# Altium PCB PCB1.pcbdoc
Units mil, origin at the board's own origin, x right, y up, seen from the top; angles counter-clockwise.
Board outline 3149.61 x 1574.8 mil, 2 copper layers (Top Layer, Bottom Layer); 16 components, 32 nets, 99 pads, 36 vias.
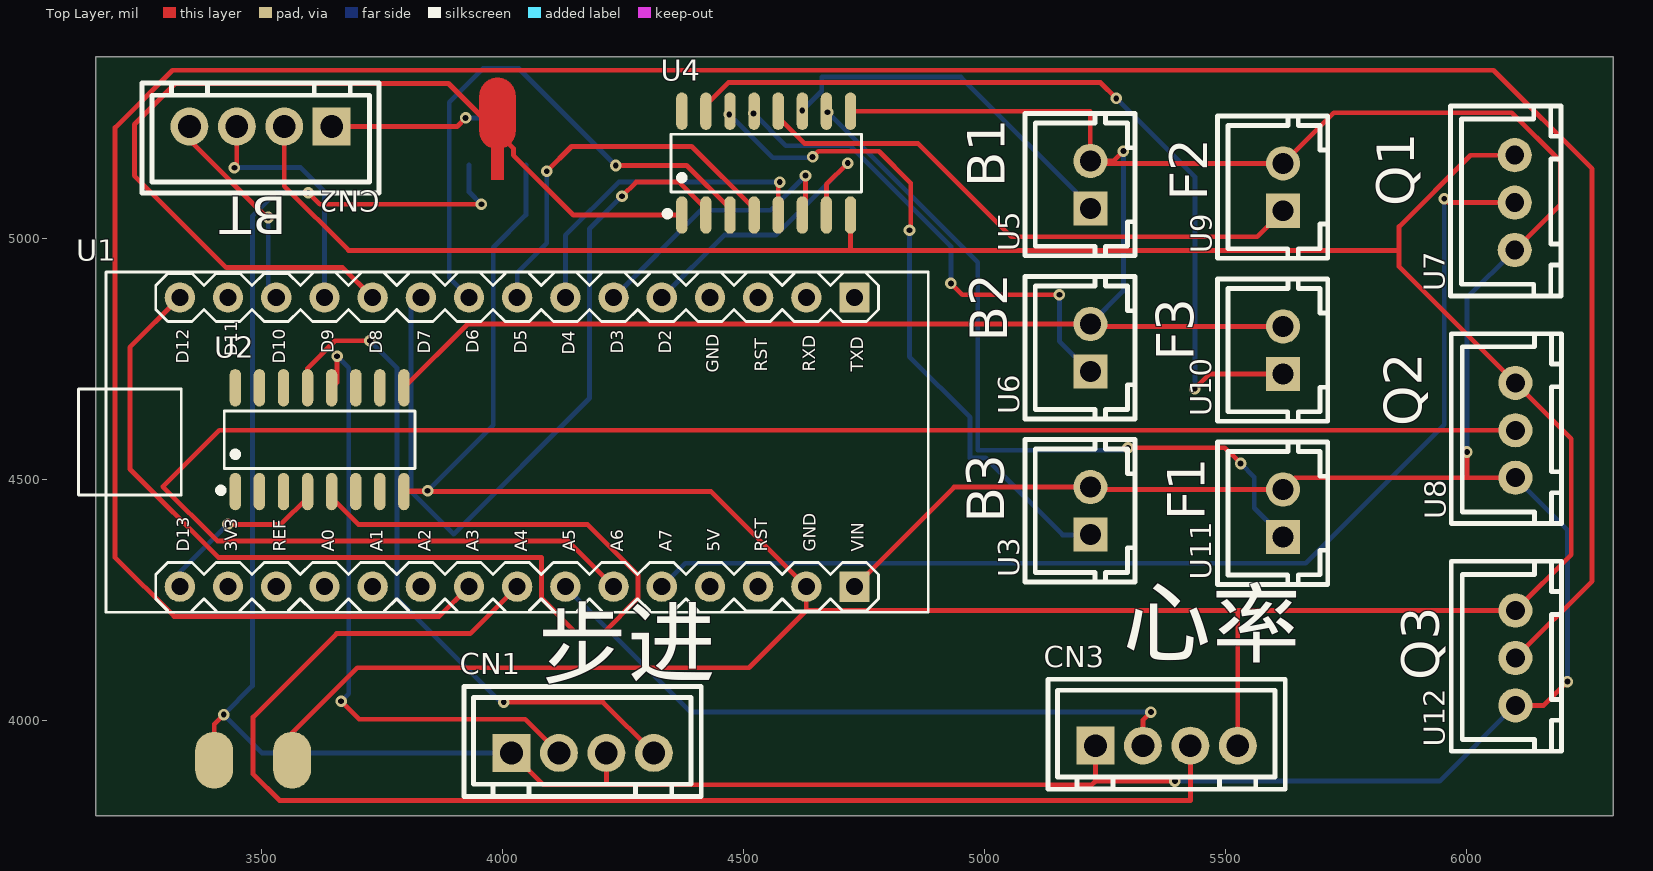
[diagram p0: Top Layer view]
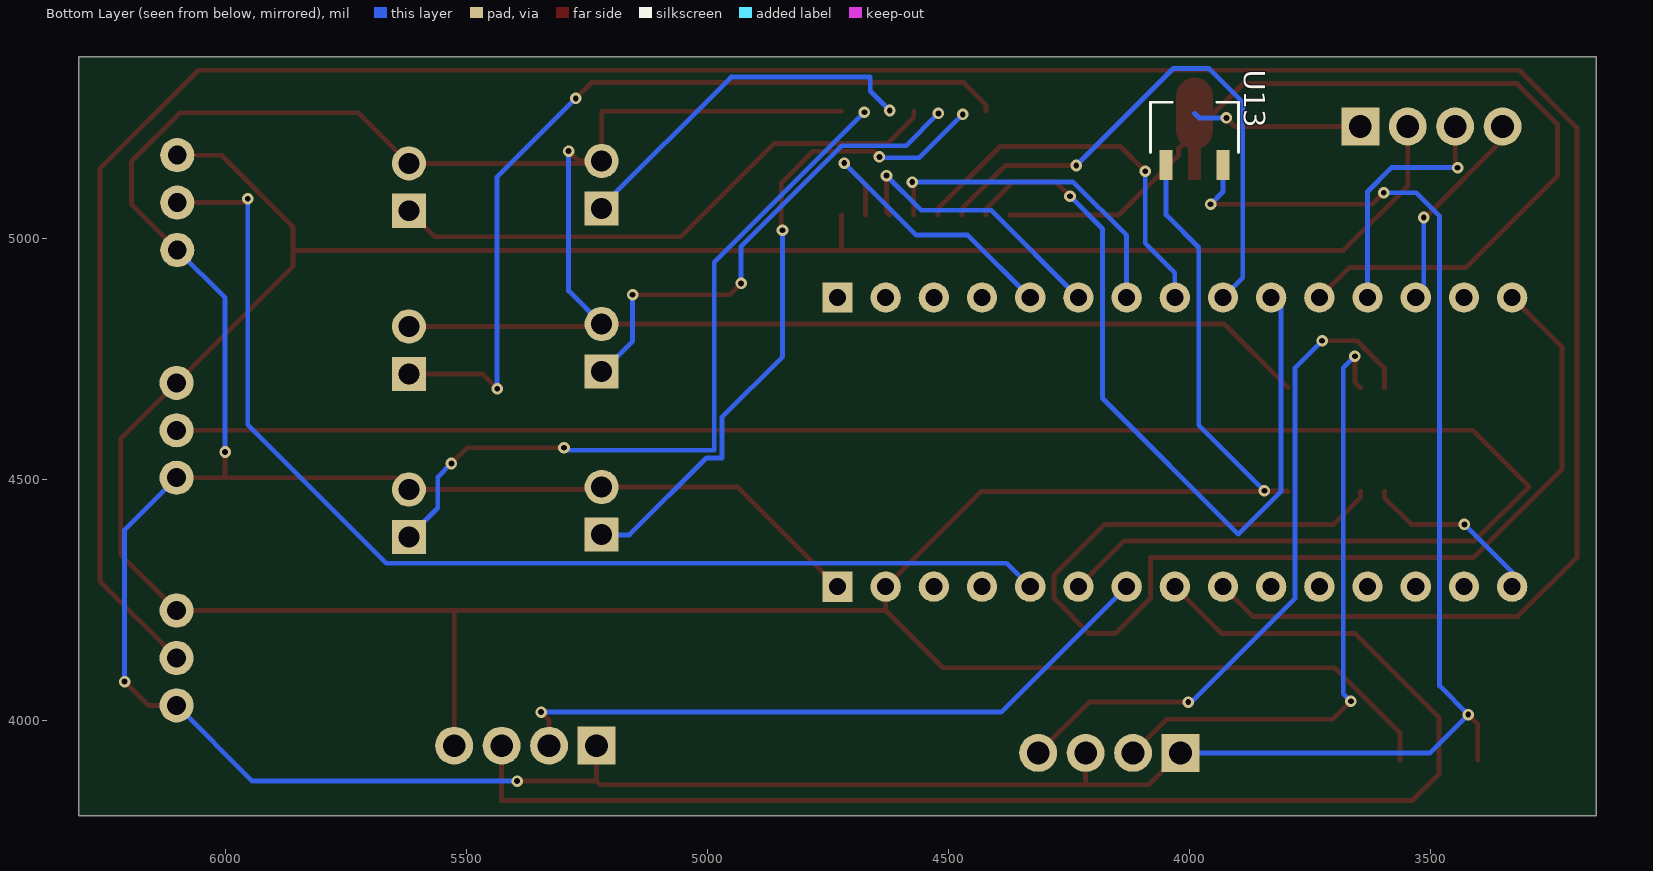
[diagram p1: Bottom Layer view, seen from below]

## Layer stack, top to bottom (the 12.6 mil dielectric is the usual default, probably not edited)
Top Solder: solder mask 0.4, Solder Resist, Dk 3.5
Top Layer: signal copper 1.4
Dielectric 1: dielectric 12.6, FR-4, Dk 4.8
Bottom Layer: signal copper 1.4
Bottom Solder: solder mask 0.4, Solder Resist, Dk 3.5

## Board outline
3154.76,3802.62 6304.37,3802.62 6304.37,5377.42 3154.76,5377.42

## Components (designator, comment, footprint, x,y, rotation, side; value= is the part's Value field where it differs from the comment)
CN1 "" CONN-TH_XH-4A 4165.55,3932.62 r0 top
CN2 "" CONN-TH_XH-4A 3497.17,5232.43 r180 top
CN3 "" CONN-TH_XH-4A 5377.4,3947.62 r0 top
U1 "" COMM-TH_ARDUINO_NANO 4029.76,4577.62 r0 top
U2 "" SOIC-16_L9.9-W3.9-P1.27-LS6.0-BL 3619.76,4582.62 r0 top
U3 "" CONN-TH_2P-P2.50_XH-2A_3045048 5219.09,4435.1 r90 top
U4 "" SOIC-16_L9.9-W3.9-P1.27-LS6.0-BL 4546.43,5156.5 r0 top
U5 "" CONN-TH_2P-P2.50_XH-2A_3045048 5219.09,5111.79 r90 top
U6 "" CONN-TH_2P-P2.50_XH-2A_3045048 5219.09,4773.44 r90 top
U7 "" CONN-TH_XH-3A 6099.76,5074.56 r90 top
U8 "" CONN-TH_XH-3A 6101.09,4602.12 r90 top
U9 "" CONN-TH_2P-P2.50_XH-2A_3045048 5619.09,5106.75 r90 top
U10 "" CONN-TH_2P-P2.50_XH-2A_3045048 5619.09,4768.41 r90 top
U11 "" CONN-TH_2P-P2.50_XH-2A_3045048 5619.09,4430.06 r90 top
U12 "" CONN-TH_XH-3A 6101.09,4129.67 r90 top
U13 "" SOT-89-3_L4.5-W2.5-P1.50-LS4.2-BR 3988.88,5206.15 r270 bottom

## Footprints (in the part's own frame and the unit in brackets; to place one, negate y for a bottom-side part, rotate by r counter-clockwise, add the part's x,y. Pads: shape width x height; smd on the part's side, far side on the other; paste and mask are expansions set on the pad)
COMM-TH_ARDUINO_NANO [mm]
  rect 1.6x1.6 hole 0.9: 1(17.78,7.62) 30(17.78,-7.62)
  round 1.6 hole 0.9: 2(15.24,7.62) 4(10.16,7.62) 6(5.08,7.62) 8(0,7.62) 10(-5.08,7.62) 12(-10.16,7.62) 14(-15.24,7.62) 15(-17.78,7.62) 16(-17.78,-7.62) 18(-12.7,-7.62) 20(-7.62,-7.62) 22(-2.54,-7.62) 24(2.54,-7.62) 26(7.62,-7.62) 28(12.7,-7.62) 29(15.24,-7.62)
  round 1.6 hole 0.9 copper offset 0,0: 3(12.7,7.62)
  round 1.6 hole 0.9 copper offset 0.001,0: 5(7.619,7.62) 7(2.539,7.62) 9(-2.541,7.62) 11(-7.621,7.62) 13(-12.701,7.62)
  round 1.6 hole 0.9 copper offset -0.001,0: 17(-15.239,-7.62) 19(-10.159,-7.62) 21(-5.079,-7.62) 23(0.001,-7.62) 25(5.081,-7.62) 27(10.161,-7.62)
  silkscreen extent -23.11,-8.97 21.67,8.97
CONN-TH_2P-P2.50_XH-2A_3045048 [mm]
  rect 1.8x1.8 hole 1.1: 1(-1.25,0)
  round 1.8 hole 1.1: 2(1.25,0)
  silkscreen extent -3.75,-2.35 3.75,3.45
CONN-TH_XH-3A [mm]
  round 1.8 hole 1: 1(-2.5,0) 2(0,0) 3(2.5,0)
  silkscreen extent -4.92,-2.44 5.09,3.38
CONN-TH_XH-4A [mm]
  rect 2x2 hole 1.2: 1(-3.75,0)
  round 2 hole 1.2: 2(-1.25,0) 3(1.25,0) 4(3.75,0)
  silkscreen extent -6.25,-2.3 6.25,3.5
SOIC-16_L9.9-W3.9-P1.27-LS6.0-BL [mil]
  oval 23.7x77.6 smd: 1(-175,-107.7) 2(-125,-107.7) 3(-75,-107.7) 4(-25,-107.7) 5(25,-107.7) 6(75,-107.7) 7(125,-107.7) 8(175,-107.7) 9(175,107.7) 10(125,107.7) 11(75,107.7) 12(25,107.7) 13(-25,107.7) 14(-75,107.7) 15(-125,107.7) 16(-175,107.7)
  silkscreen extent -211,-111 198,60
SOT-89-3_L4.5-W2.5-P1.50-LS4.2-BR [mm]
  rect 1.575x0.672 smd: 1(1.356,-1.5) 3(1.356,1.5)
  Bottom Layer region: -2.283,0.95 -0.429,0.95 -0.384,0.949 -0.34,0.946 -0.296,0.94 -0.252,0.933 -0.208,0.924 -0.165,0.912 -0.123,0.899 -0.081,0.884 -0.04,0.866 0,0.847 0.04,0.826 0.078,0.803 0.115,0.779 0.151,0.752 0.185,0.724 0.219,0.695 0.251,0.664 0.281,0.631 0.31,0.597 0.337,0.562 0.362,0.525 0.386,0.488 0.408,0.449 0.428,0.409 0.447,0.33 2.144,0.33 2.144,-0.33 0.447,-0.33 0.428,-0.409 0.408,-0.449 0.386,-0.488 0.362,-0.526 0.337,-0.562 0.31,-0.597 0.281,-0.631 0.251,-0.664 0.219,-0.695 0.185,-0.725 0.151,-0.753 0.115,-0.779 0.078,-0.804 0.04,-0.827 0,-0.848 -0.04,-0.867 -0.081,-0.884 -0.123,-0.899 -0.165,-0.913 -0.208,-0.924 -0.252,-0.934 -0.296,-0.941 -0.34,-0.946 -0.384,-0.949 -0.429,-0.95 -2.283,-0.95 -2.328,-0.949 -2.372,-0.946 -2.416,-0.941 -2.46,-0.934 -2.504,-0.924 -2.547,-0.913 -2.589,-0.899 -2.631,-0.884 -2.672,-0.867 -2.713,-0.848 -2.752,-0.827 -2.79,-0.804 -2.827,-0.779 -2.863,-0.753 -2.898,-0.725 -2.931,-0.695 -2.963,-0.664 -2.993,-0.631 -3.022,-0.597 -3.049,-0.562 -3.075,-0.526 -3.098,-0.488 -3.12,-0.449 -3.141,-0.409 -3.159,-0.369 -3.175,-0.327 -3.189,-0.285 -3.202,-0.242 -3.212,-0.199 -3.22,-0.155 -3.227,-0.111 -3.231,-0.067 -3.233,-0.022 -3.233,0.022 -3.231,0.067 -3.227,0.111 -3.22,0.155 -3.212,0.199 -3.202,0.242 -3.189,0.285 -3.175,0.327 -3.159,0.369 -3.141,0.409 -3.12,0.449 -3.098,0.488 -3.075,0.525 -3.049,0.562 -3.022,0.597 -2.993,0.631 -2.963,0.664 -2.931,0.695 -2.898,0.724 -2.863,0.752 -2.827,0.779 -2.79,0.803 -2.752,0.826 -2.713,0.847 -2.672,0.866 -2.631,0.884 -2.589,0.899 -2.547,0.912 -2.504,0.924 -2.46,0.933 -2.416,0.94 -2.372,0.946 -2.328,0.949
  silkscreen extent -1.95,-2.33 0.7,2.33

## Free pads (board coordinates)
  oval 78.74x118.11 smd: ""(3401.05,3917.38) ""(3562.69,3917.38)

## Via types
v1: diameter 24.02, hole 12.01, Top Layer to Bottom Layer, 36 vias

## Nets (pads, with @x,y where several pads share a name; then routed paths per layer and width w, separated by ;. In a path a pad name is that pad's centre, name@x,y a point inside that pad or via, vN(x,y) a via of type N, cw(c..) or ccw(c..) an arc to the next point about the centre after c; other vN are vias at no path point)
$1N1078: U1.5 U2.7 U4.7 | length 627.3
  Top Layer w10: U4.7 4671.43,5112.35 v1(4715.59,5156.5)
  Bottom Layer w10: U1.5@4329.76,4877.62 4459.25,5007.1 4566.18,5007.1 v1(4715.59,5156.5)
$1N1083: U1.6 U2.6 U4.6 | length 587.4
  Top Layer w10: U4.6 4627.98,5055.35 v1(4627.98,5130.55)
  Bottom Layer w10: U1.6 4410.74,5058.59 4556.02,5058.59 v1(4627.98,5130.55)
$1N1088: U1.7 U4.5 | length 689
  Top Layer w10: U4.5 4571.43,5113.98 v1(4574.55,5117.1)
  Bottom Layer w10: U1.7@4129.76,4877.62 4129.76,5006.45 4240.41,5117.1 v1(4574.55,5117.1)
$1N1093: U1.8 U4.4 | length 805.3
  Top Layer w10: v1(4091.22,5139.75) 4142.47,5191 4391.89,5191 4521.43,5061.45 U4.4
  Bottom Layer w10: U1.8 4029.76,4928.87 4091.22,4990.32 v1(4091.22,5139.75)
$1N1098: U1.9 U2.3 U4.3 | length 1166.7
  Top Layer w10: v1(4234.42,5151.59) 4381.3,5151.59 4471.43,5061.45 U4.3
  Bottom Layer w10: U1.9@3929.76,4877.62 3888.93,4918.45 3888.93,5282.87 3958.58,5352.52 4033.49,5352.52 v1(4234.42,5151.59)
$1N1103: U1.10 U2.2 U4.2 | length 1603.8
  Top Layer w10: v1(4247.17,5087.85) 4276.42,5117.1 4365.79,5117.1 4421.43,5061.45 U4.2
  Bottom Layer w10: U1.10 3809.53,4857.38 3809.53,4474.89 3897.7,4386.71 4179.76,4668.77 4179.76,5020.44 v1(4247.17,5087.85)
$1N1108: U1.11 U2.1 U4.1 | length 1997.7
  Top Layer w10: U1.11@3729.76,4877.62 3667.74,4939.64 3426.4,4939.64 3235.36,5130.68 3235.36,5236.61 3320.46,5321.71 3887.25,5321.71 4021.88,5187.08 4021.88,5173.07 4146.15,5048.8 U4.1
$1N1790: U1.15 U2.5 | length 2437.4
  Top Layer w10: U1.15 3226.15,4774 3226.15,4521.73 3409.69,4338.19 4080.22,4338.19 4080.22,4253.31 4153.27,4180.26 4207.17,4180.26 4280.22,4253.31 4280.22,4301.92 4175.33,4406.81 3700.22,4406.81 3644.76,4462.27 U2.5
$1N1795: U1.16 U2.4 | length 371.8
  Top Layer w10: v1(3428.75,4406.81) 3539.31,4406.81 3594.76,4462.27 U2.4
  Bottom Layer w10: U1.16 3329.76,4307.82 v1(3428.75,4406.81)
$1N2846: CN1.4 U2.13 | length 1416.9
  Top Layer w10: U2.13 3594.76,4730.76 3651.74,4787.73 v1(3724.13,4787.73) ; v1(4002.02,4038.08) 4207.73,4038.08 CN1.4
  Bottom Layer w10: v1(3724.13,4787.73) 3780.22,4731.64 3780.22,4253.31 3995.46,4038.08 v1(4002.02,4038.08)
$1N4027: U1.26 U7.2 | length 2381.4
  Top Layer w10: v1(5953.58,5082.61) 5961.64,5074.55 U7.2
  Bottom Layer w10: U1.26 4378.36,4326.22 5665.93,4326.22 5953.58,4613.86 v1(5953.58,5082.61)
$1N4520: CN3.2 U1.24 | length 1399.4
  Top Layer w10: CN3.2 5328.19,4000.83 v1(5344.73,4017.37)
  Bottom Layer w10: U1.24 4390.01,4017.37 v1(5344.73,4017.37)
$1N4548: CN3.3 U1.23 | length 2859.5
  Top Layer w10: U1.23 3932.41,4180.26 3655.07,4180.26 3481.87,4007.06 3481.87,3888.76 3536.77,3833.86 5426.61,3833.86 CN3.3
$1N4816: CN2.1 | length 355.3
  Top Layer w10: CN2.1 3904.91,5232.43 v1(3922.71,5250.23)
  Bottom Layer w10: v1(3922.71,5250.23) 3979.58,5250.23 3988.89,5259.54
$1N4934: CN2.4 U1.13 | length 431.1
  Top Layer w10: CN2.4 3349.53,5204.61 3510.45,5043.7 v1(3513.3,5043.7)
  Bottom Layer w10: v1(3513.3,5043.7) 3513.3,4894.08 U1.13@3529.76,4877.62
$1N4935: CN2.3 U1.12 | length 514.6
  Top Layer w10: v1(3443.06,5147.1) 3447.96,5152 CN2.3
  Bottom Layer w10: v1(3443.06,5147.1) 3580.27,5147.1 3629.76,5097.6 U1.12
+5V: CN1.1 CN1.3 CN3.1 pad.@3401.05,3917.38 U1.30 U2.9 U3.2 U4.9 U5.2 U6.2 U7.1 U8.1 U9.2 U10.2 U11.2 U12.1 U13.3 | length 11520
  Top Layer w10: pad.@3401.05,3917.38 3401.05,3992.49 v1(3420.65,4012.09) ; v1(3596.2,5095.15) 3620.32,5071.03 v1(3955.41,5071.03) ; U2.9 3927.1,4822.65 U6.2 5224.13,4817.62 U10.2 ; CN1.1 4083.98,3866.55 4214.76,3866.55 ; CN1.3 4214.76,3866.55 ; U4.9 5219.09,5264.2 U5.2 ; U1.30 4936.46,4484.31 U3.2 5224.13,4479.27 U11.2 5643.51,4503.69 6000.43,4503.69 ; CN3.1 5229.76,3874.05 ; v1(5287.77,5181.47) 5267.3,5161 U5.2 ; v1(5394.59,3874.05) 5229.76,3874.05 ; v1(6000.43,4557.05) 6000.43,4503.69 ; U7.1 6194.82,5071.19 6194.82,5159.9 6093.65,5261.07 5724.2,5261.07 U9.2 5224.13,5155.96 U5.2 ; U12.1 6159.57,4031.25 v1(6209.02,4080.71) ; U8.1 6000.43,4503.69 ; 4214.76,3866.55 5222.26,3866.55 5229.76,3874.05
  Bottom Layer w10: v1(3596.2,5095.15) 3528.74,5095.15 3480.22,5046.64 3480.22,4071.66 v1(3420.65,4012.09) 3500.13,3932.62 CN1.1 ; U13.3 3929.83,5096.6 v1(3955.41,5071.03) ; U6.2 5287.77,4891.33 v1(5287.77,5181.47) ; v1(5394.59,3874.05) 5943.89,3874.05 U12.1 ; v1(6000.43,4557.05) 6000.43,4876.8 U7.1 ; U8.1 6209.02,4395.76 v1(6209.02,4080.71)
A-: CN1.2 U2.12 | length 1299.3
  Top Layer w10: U2.12 3655.94,4701.5 v1(3655.94,4755.92) ; v1(3664.39,4039.81) 3701.66,4002.53 4046.43,4002.53 CN1.2
  Bottom Layer w10: v1(3655.94,4755.92) 3680.22,4731.65 3680.22,4055.64 v1(3664.39,4039.81)
B1-: U2.11 U4.11 U5.1 | length 759.8
  Bottom Layer w10: v1(4621.24,5265.72) 4661.62,5306.11 4661.62,5335.08 4950.46,5335.08 U5.1@5222.61,5062.92
B2-: U4.13 U6.1 | length 1013.7
  Top Layer w10: v1(4929.8,4906.91) 4953.51,4883.21 v1(5154.99,4883.21)
  Bottom Layer w10: v1(4520.28,5259.58) 4587.18,5192.67 4720.83,5192.67 4929.8,4983.69 v1(4929.8,4906.91) ; v1(5154.99,4883.21) 5154.99,4787.08 U6.1@5212.93,4729.13
B3-: U2.14 U3.1 U4.14 | length 1377.8
  Top Layer w10: v1(4642.72,5169.3) 4654.39,5180.96 4780.56,5180.96 4846.4,5115.12 v1@4846.4,5020.93
  Bottom Layer w10: v1(4469.99,5257.53) 4559.98,5167.54 v1@4645.36,5167.54 ; v1(4843.77,5017.42) 4843.77,4754.92 4969.57,4629.11 4969.57,4544.76 5001.53,4544.76 5161.41,4384.88 U3.1@5213.81,4384.88
BY: U1.14
C1: U1.21
C2: U1.20
F1-: U2.10 U4.10 U11.1 | length 1574.1
  Top Layer w10: v1(5297.23,4566.02) 5498.18,4566.02 v1(5530.95,4533.25)
  Bottom Layer w10: v1(4673.91,5262.21) 4985.57,4950.55 4985.57,4560.76 5291.09,4560.76 v1@5299.87,4569.54 ; v1(5530.95,4533.25) 5559.32,4504.88 5559.32,4440.79 U11.1@5611.72,4388.39
F2-: U4.12 U9.1 | length 1185.2
  Top Layer w10: U4.12 4571.43,5251.55 4626.03,5196.96 4861.88,5196.96 5055.06,5003.77 5565.32,5003.77 U9.1
F3-: U2.15 U4.15 U10.1 | length 1763.3
  Top Layer w10: U4.15 4421.43,5276.85 4468.16,5323.58 5240.18,5323.58 v1(5272.99,5290.77) ; v1(5435.96,4688.12) 5467.04,4719.2 U10.1
  Bottom Layer w10: v1(5272.99,5290.77) 5435.96,5127.8 v1(5435.96,4688.12)
F4-: U2.16 U4.16
GND: CN2.2 CN3.4 pad.@3562.69,3917.38 U1.29 U2.8 U4.8 U7.3 U8.3 U12.3 U13.1 | length 8617.3
  Top Layer w10: CN2.2 3546.38,5108.96 3679.93,4975.4 4721.43,4975.4 ; pad.@3562.69,3917.38 3562.69,3974.13 3697.73,4109.17 4510.83,4109.17 4629.76,4228.1 ; v1(3843.88,4476.56) 3796.4,4476.56 U2.8 4432.46,4474.92 U1.29 4629.76,4228.1 ; U4.8 4721.43,4975.4 ; CN3.4 5525.04,4228.1 ; U7.3 6007.93,5172.98 5859.87,5024.92 5859.87,4975.4 ; 4629.76,4228.1 5525.04,4228.1 ; 4721.43,4975.4 5859.87,4975.4 ; 5525.04,4228.1 U12.3 6217.1,4344.11 6217.1,4584.53 U8.3 5859.87,4941.76 5859.87,4975.4
  Bottom Layer w10: v1(3843.88,4476.56) 3980.22,4612.9 3980.22,4981.45 4047.94,5049.17 U13.1
Q2: U1.25 U8.2 | length 3875.9
  Top Layer w10: U1.25 4134.88,4372.5 3407.47,4372.5 3294.7,4485.27 3411.54,4602.11 U8.2
Q3: U1.22 U12.2 | length 5982.3
  Top Layer w10: U1.22 3867.95,4215.8 3317.73,4215.8 3195.46,4338.07 3195.46,5230.1 3314.53,5349.16 6055.68,5349.16 6260.34,5144.51 6260.34,4288.91 U12.2
"": U1.1 U1.2 U1.3 U1.4 U1.17 U1.18 U1.19 U1.27 U1.28

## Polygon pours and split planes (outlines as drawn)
GND on Top Layer (solid, remove dead copper, pour order 0): 3000,3000 7266.5,3000 7266.5,6033.11 3000,6033.11

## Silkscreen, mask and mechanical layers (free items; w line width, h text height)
Top Overlay:
  text "B1" at 5041.16,5106.42 h77.88 r90
  text "BT" at 3551.77,5086.38 h77.88 r180
  text "F2" at 5461.63,5078.02 h77.88 r90
  text "Q1" at 5891.49,5067.37 h77.88 r90
  text "B2" at 5046.82,4785.67 h77.88 r90
  text "F3" at 5433.98,4746.17 h77.88 r90
  text "Q2" at 5906.92,4610.35 h77.88 r90
  text "F1" at 5456.83,4415.85 h77.88 r90
  text "B3" at 5040.89,4410.37 h77.88 r90
  text "心率" at 5284.89,4136.04 h135.94
  text "步进" at 4072.18,4095.44 h135.94
  text "Q3" at 5943.01,4083.4 h77.88 r90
